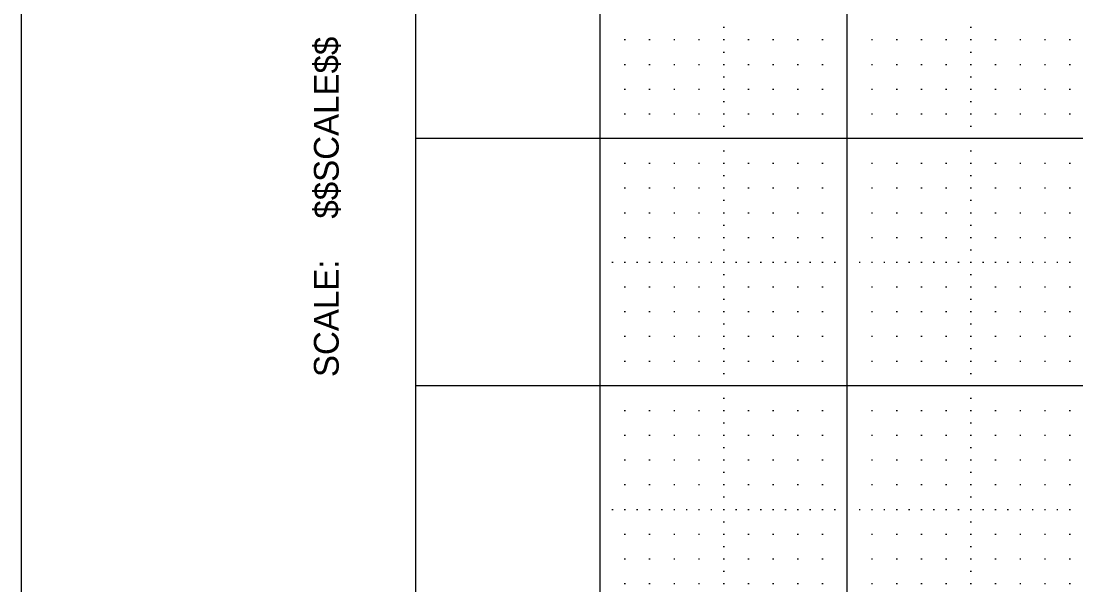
# Model space of a CAD drawing. Extents: x 0 to 34.3, y 0 to 22.
# Drawn here: x 0 to 4.268, y 3.214 to 5.495 of the extents above; entities that cross this region are included whole.
import ezdxf

# ---------------------------------------------------------------- set-up
doc = ezdxf.new("R2010")
doc.units = 0
for name, color, linetype in [('Level 1', 7, 'Continuous'), ('Level 5', 7, 'Continuous'), ('Level 63', 7, 'Continuous'), ('R_Border_Dark', 7, 'Continuous')]:
    doc.layers.add(name, color=color, linetype=linetype)

msp = doc.modelspace()

# ---------------------------------------------------------------- linework, layer by layer
at = {"layer": 'Level 1'}
msp.add_line((1.597, 0.726), (1.597, 21.272), dxfattribs=at)
msp.add_lwpolyline([(2.343, 9.02), (32.343, 9.02), (32.343, 1.02), (2.343, 1.02)], close=True, dxfattribs=at)
at = {"layer": 'Level 5'}
for p, q in [((2.8405, 5.47), (2.8455, 5.47)), ((3.8405, 5.47), (3.8455, 5.47)), ((2.4405, 5.42), (2.4455, 5.42)), ((2.5405, 5.42), (2.5455, 5.42)), ((2.6405, 5.42), (2.6455, 5.42)), ((2.7405, 5.42), (2.7455, 5.42)), ((2.8405, 5.42), (2.8455, 5.42)), ((2.9405, 5.42), (2.9455, 5.42)), ((3.0405, 5.42), (3.0455, 5.42)), ((3.1405, 5.42), (3.1455, 5.42)), ((3.2405, 5.42), (3.2455, 5.42)), ((3.4405, 5.42), (3.4455, 5.42)), ((3.5405, 5.42), (3.5455, 5.42)), ((3.6405, 5.42), (3.6455, 5.42)), ((3.7405, 5.42), (3.7455, 5.42)), ((3.8405, 5.42), (3.8455, 5.42)), ((3.9405, 5.42), (3.9455, 5.42)), ((4.0405, 5.42), (4.0455, 5.42)), ((4.1405, 5.42), (4.1455, 5.42)), ((4.2405, 5.42), (4.2455, 5.42)), ((2.8405, 5.37), (2.8455, 5.37)), ((3.8405, 5.37), (3.8455, 5.37)), ((2.4405, 5.32), (2.4455, 5.32)), ((2.5405, 5.32), (2.5455, 5.32)), ((2.6405, 5.32), (2.6455, 5.32)), ((2.7405, 5.32), (2.7455, 5.32)), ((2.8405, 5.32), (2.8455, 5.32)), ((2.9405, 5.32), (2.9455, 5.32)), ((3.0405, 5.32), (3.0455, 5.32)), ((3.1405, 5.32), (3.1455, 5.32)), ((3.2405, 5.32), (3.2455, 5.32)), ((3.4405, 5.32), (3.4455, 5.32)), ((3.5405, 5.32), (3.5455, 5.32)), ((3.6405, 5.32), (3.6455, 5.32)), ((3.7405, 5.32), (3.7455, 5.32)), ((3.8405, 5.32), (3.8455, 5.32)), ((3.9405, 5.32), (3.9455, 5.32)), ((4.0405, 5.32), (4.0455, 5.32)), ((4.1405, 5.32), (4.1455, 5.32)), ((4.2405, 5.32), (4.2455, 5.32)), ((2.8405, 5.27), (2.8455, 5.27)), ((3.8405, 5.27), (3.8455, 5.27)), ((2.4405, 5.22), (2.4455, 5.22)), ((2.5405, 5.22), (2.5455, 5.22)), ((2.6405, 5.22), (2.6455, 5.22)), ((2.7405, 5.22), (2.7455, 5.22)), ((2.8405, 5.22), (2.8455, 5.22)), ((2.9405, 5.22), (2.9455, 5.22)), ((3.0405, 5.22), (3.0455, 5.22)), ((3.1405, 5.22), (3.1455, 5.22)), ((3.2405, 5.22), (3.2455, 5.22)), ((3.4405, 5.22), (3.4455, 5.22)), ((3.5405, 5.22), (3.5455, 5.22)), ((3.6405, 5.22), (3.6455, 5.22)), ((3.7405, 5.22), (3.7455, 5.22)), ((3.8405, 5.22), (3.8455, 5.22)), ((3.9405, 5.22), (3.9455, 5.22)), ((4.0405, 5.22), (4.0455, 5.22)), ((4.1405, 5.22), (4.1455, 5.22)), ((4.2405, 5.22), (4.2455, 5.22)), ((2.8405, 5.17), (2.8455, 5.17)), ((3.8405, 5.17), (3.8455, 5.17)), ((2.4405, 5.12), (2.4455, 5.12)), ((2.5405, 5.12), (2.5455, 5.12)), ((2.6405, 5.12), (2.6455, 5.12)), ((2.7405, 5.12), (2.7455, 5.12)), ((2.8405, 5.12), (2.8455, 5.12)), ((2.9405, 5.12), (2.9455, 5.12)), ((3.0405, 5.12), (3.0455, 5.12)), ((3.1405, 5.12), (3.1455, 5.12)), ((3.2405, 5.12), (3.2455, 5.12)), ((3.4405, 5.12), (3.4455, 5.12)), ((3.5405, 5.12), (3.5455, 5.12)), ((3.6405, 5.12), (3.6455, 5.12)), ((3.7405, 5.12), (3.7455, 5.12)), ((3.8405, 5.12), (3.8455, 5.12)), ((3.9405, 5.12), (3.9455, 5.12)), ((4.0405, 5.12), (4.0455, 5.12)), ((4.1405, 5.12), (4.1455, 5.12)), ((4.2405, 5.12), (4.2455, 5.12)), ((2.8405, 5.07), (2.8455, 5.07)), ((3.8405, 5.07), (3.8455, 5.07)), ((2.8405, 4.97), (2.8455, 4.97)), ((3.8405, 4.97), (3.8455, 4.97)), ((2.4405, 4.92), (2.4455, 4.92)), ((2.5405, 4.92), (2.5455, 4.92)), ((2.6405, 4.92), (2.6455, 4.92)), ((2.7405, 4.92), (2.7455, 4.92)), ((2.8405, 4.92), (2.8455, 4.92)), ((2.9405, 4.92), (2.9455, 4.92)), ((3.0405, 4.92), (3.0455, 4.92)), ((3.1405, 4.92), (3.1455, 4.92)), ((3.2405, 4.92), (3.2455, 4.92)), ((3.4405, 4.92), (3.4455, 4.92)), ((3.5405, 4.92), (3.5455, 4.92)), ((3.6405, 4.92), (3.6455, 4.92)), ((3.7405, 4.92), (3.7455, 4.92)), ((3.8405, 4.92), (3.8455, 4.92)), ((3.9405, 4.92), (3.9455, 4.92)), ((4.0405, 4.92), (4.0455, 4.92)), ((4.1405, 4.92), (4.1455, 4.92)), ((4.2405, 4.92), (4.2455, 4.92)), ((2.8405, 4.87), (2.8455, 4.87)), ((3.8405, 4.87), (3.8455, 4.87)), ((2.4405, 4.82), (2.4455, 4.82)), ((2.5405, 4.82), (2.5455, 4.82)), ((2.6405, 4.82), (2.6455, 4.82)), ((2.7405, 4.82), (2.7455, 4.82)), ((2.8405, 4.82), (2.8455, 4.82)), ((2.9405, 4.82), (2.9455, 4.82)), ((3.0405, 4.82), (3.0455, 4.82)), ((3.1405, 4.82), (3.1455, 4.82)), ((3.2405, 4.82), (3.2455, 4.82)), ((3.4405, 4.82), (3.4455, 4.82)), ((3.5405, 4.82), (3.5455, 4.82)), ((3.6405, 4.82), (3.6455, 4.82)), ((3.7405, 4.82), (3.7455, 4.82)), ((3.8405, 4.82), (3.8455, 4.82)), ((3.9405, 4.82), (3.9455, 4.82)), ((4.0405, 4.82), (4.0455, 4.82)), ((4.1405, 4.82), (4.1455, 4.82)), ((4.2405, 4.82), (4.2455, 4.82)), ((2.8405, 4.77), (2.8455, 4.77)), ((3.8405, 4.77), (3.8455, 4.77)), ((2.4405, 4.72), (2.4455, 4.72)), ((2.5405, 4.72), (2.5455, 4.72)), ((2.6405, 4.72), (2.6455, 4.72)), ((2.7405, 4.72), (2.7455, 4.72)), ((2.8405, 4.72), (2.8455, 4.72)), ((2.9405, 4.72), (2.9455, 4.72)), ((3.0405, 4.72), (3.0455, 4.72)), ((3.1405, 4.72), (3.1455, 4.72)), ((3.2405, 4.72), (3.2455, 4.72)), ((3.4405, 4.72), (3.4455, 4.72)), ((3.5405, 4.72), (3.5455, 4.72)), ((3.6405, 4.72), (3.6455, 4.72)), ((3.7405, 4.72), (3.7455, 4.72)), ((3.8405, 4.72), (3.8455, 4.72)), ((3.9405, 4.72), (3.9455, 4.72)), ((4.0405, 4.72), (4.0455, 4.72)), ((4.1405, 4.72), (4.1455, 4.72)), ((4.2405, 4.72), (4.2455, 4.72)), ((2.8405, 4.67), (2.8455, 4.67)), ((3.8405, 4.67), (3.8455, 4.67)), ((2.4405, 4.62), (2.4455, 4.62)), ((2.5405, 4.62), (2.5455, 4.62)), ((2.6405, 4.62), (2.6455, 4.62)), ((2.7405, 4.62), (2.7455, 4.62)), ((2.8405, 4.62), (2.8455, 4.62)), ((2.9405, 4.62), (2.9455, 4.62)), ((3.0405, 4.62), (3.0455, 4.62)), ((3.1405, 4.62), (3.1455, 4.62)), ((3.2405, 4.62), (3.2455, 4.62)), ((3.4405, 4.62), (3.4455, 4.62)), ((3.5405, 4.62), (3.5455, 4.62)), ((3.6405, 4.62), (3.6455, 4.62)), ((3.7405, 4.62), (3.7455, 4.62)), ((3.8405, 4.62), (3.8455, 4.62)), ((3.9405, 4.62), (3.9455, 4.62)), ((4.0405, 4.62), (4.0455, 4.62)), ((4.1405, 4.62), (4.1455, 4.62)), ((4.2405, 4.62), (4.2455, 4.62)), ((2.8405, 4.57), (2.8455, 4.57)), ((3.8405, 4.57), (3.8455, 4.57)), ((2.3905, 4.52), (2.3955, 4.52)), ((2.4405, 4.52), (2.4455, 4.52)), ((2.4905, 4.52), (2.4955, 4.52)), ((2.5405, 4.52), (2.5455, 4.52)), ((2.5905, 4.52), (2.5955, 4.52)), ((2.6405, 4.52), (2.6455, 4.52)), ((2.6905, 4.52), (2.6955, 4.52)), ((2.7405, 4.52), (2.7455, 4.52)), ((2.7905, 4.52), (2.7955, 4.52)), ((2.8405, 4.52), (2.8455, 4.52)), ((2.8905, 4.52), (2.8955, 4.52)), ((2.9405, 4.52), (2.9455, 4.52)), ((2.9905, 4.52), (2.9955, 4.52)), ((3.0405, 4.52), (3.0455, 4.52)), ((3.0905, 4.52), (3.0955, 4.52)), ((3.1405, 4.52), (3.1455, 4.52)), ((3.1905, 4.52), (3.1955, 4.52)), ((3.2405, 4.52), (3.2455, 4.52)), ((3.2905, 4.52), (3.2955, 4.52)), ((3.3905, 4.52), (3.3955, 4.52)), ((3.4405, 4.52), (3.4455, 4.52)), ((3.4905, 4.52), (3.4955, 4.52)), ((3.5405, 4.52), (3.5455, 4.52)), ((3.5905, 4.52), (3.5955, 4.52)), ((3.6405, 4.52), (3.6455, 4.52)), ((3.6905, 4.52), (3.6955, 4.52)), ((3.7405, 4.52), (3.7455, 4.52)), ((3.7905, 4.52), (3.7955, 4.52)), ((3.8405, 4.52), (3.8455, 4.52)), ((3.8905, 4.52), (3.8955, 4.52)), ((3.9405, 4.52), (3.9455, 4.52)), ((3.9905, 4.52), (3.9955, 4.52)), ((4.0405, 4.52), (4.0455, 4.52)), ((4.0905, 4.52), (4.0955, 4.52)), ((4.1405, 4.52), (4.1455, 4.52)), ((4.1905, 4.52), (4.1955, 4.52)), ((4.2405, 4.52), (4.2455, 4.52)), ((2.8405, 4.47), (2.8455, 4.47)), ((3.8405, 4.47), (3.8455, 4.47)), ((2.4405, 4.42), (2.4455, 4.42)), ((2.5405, 4.42), (2.5455, 4.42)), ((2.6405, 4.42), (2.6455, 4.42)), ((2.7405, 4.42), (2.7455, 4.42)), ((2.8405, 4.42), (2.8455, 4.42)), ((2.9405, 4.42), (2.9455, 4.42)), ((3.0405, 4.42), (3.0455, 4.42)), ((3.1405, 4.42), (3.1455, 4.42)), ((3.2405, 4.42), (3.2455, 4.42)), ((3.4405, 4.42), (3.4455, 4.42)), ((3.5405, 4.42), (3.5455, 4.42)), ((3.6405, 4.42), (3.6455, 4.42)), ((3.7405, 4.42), (3.7455, 4.42)), ((3.8405, 4.42), (3.8455, 4.42)), ((3.9405, 4.42), (3.9455, 4.42)), ((4.0405, 4.42), (4.0455, 4.42)), ((4.1405, 4.42), (4.1455, 4.42)), ((4.2405, 4.42), (4.2455, 4.42)), ((2.8405, 4.37), (2.8455, 4.37)), ((3.8405, 4.37), (3.8455, 4.37)), ((2.4405, 4.32), (2.4455, 4.32)), ((2.5405, 4.32), (2.5455, 4.32)), ((2.6405, 4.32), (2.6455, 4.32)), ((2.7405, 4.32), (2.7455, 4.32)), ((2.8405, 4.32), (2.8455, 4.32)), ((2.9405, 4.32), (2.9455, 4.32)), ((3.0405, 4.32), (3.0455, 4.32)), ((3.1405, 4.32), (3.1455, 4.32)), ((3.2405, 4.32), (3.2455, 4.32)), ((3.4405, 4.32), (3.4455, 4.32)), ((3.5405, 4.32), (3.5455, 4.32)), ((3.6405, 4.32), (3.6455, 4.32)), ((3.7405, 4.32), (3.7455, 4.32)), ((3.8405, 4.32), (3.8455, 4.32)), ((3.9405, 4.32), (3.9455, 4.32)), ((4.0405, 4.32), (4.0455, 4.32)), ((4.1405, 4.32), (4.1455, 4.32)), ((4.2405, 4.32), (4.2455, 4.32)), ((2.8405, 4.27), (2.8455, 4.27)), ((3.8405, 4.27), (3.8455, 4.27)), ((2.4405, 4.22), (2.4455, 4.22)), ((2.5405, 4.22), (2.5455, 4.22)), ((2.6405, 4.22), (2.6455, 4.22)), ((2.7405, 4.22), (2.7455, 4.22)), ((2.8405, 4.22), (2.8455, 4.22)), ((2.9405, 4.22), (2.9455, 4.22)), ((3.0405, 4.22), (3.0455, 4.22)), ((3.1405, 4.22), (3.1455, 4.22)), ((3.2405, 4.22), (3.2455, 4.22)), ((3.4405, 4.22), (3.4455, 4.22)), ((3.5405, 4.22), (3.5455, 4.22)), ((3.6405, 4.22), (3.6455, 4.22)), ((3.7405, 4.22), (3.7455, 4.22)), ((3.8405, 4.22), (3.8455, 4.22)), ((3.9405, 4.22), (3.9455, 4.22)), ((4.0405, 4.22), (4.0455, 4.22)), ((4.1405, 4.22), (4.1455, 4.22)), ((4.2405, 4.22), (4.2455, 4.22)), ((2.8405, 4.17), (2.8455, 4.17)), ((3.8405, 4.17), (3.8455, 4.17)), ((2.4405, 4.12), (2.4455, 4.12)), ((2.5405, 4.12), (2.5455, 4.12)), ((2.6405, 4.12), (2.6455, 4.12)), ((2.7405, 4.12), (2.7455, 4.12)), ((2.8405, 4.12), (2.8455, 4.12)), ((2.9405, 4.12), (2.9455, 4.12)), ((3.0405, 4.12), (3.0455, 4.12)), ((3.1405, 4.12), (3.1455, 4.12)), ((3.2405, 4.12), (3.2455, 4.12)), ((3.4405, 4.12), (3.4455, 4.12)), ((3.5405, 4.12), (3.5455, 4.12)), ((3.6405, 4.12), (3.6455, 4.12)), ((3.7405, 4.12), (3.7455, 4.12)), ((3.8405, 4.12), (3.8455, 4.12)), ((3.9405, 4.12), (3.9455, 4.12)), ((4.0405, 4.12), (4.0455, 4.12)), ((4.1405, 4.12), (4.1455, 4.12)), ((4.2405, 4.12), (4.2455, 4.12)), ((2.8405, 4.07), (2.8455, 4.07)), ((3.8405, 4.07), (3.8455, 4.07)), ((2.8405, 3.97), (2.8455, 3.97)), ((3.8405, 3.97), (3.8455, 3.97)), ((2.4405, 3.92), (2.4455, 3.92)), ((2.5405, 3.92), (2.5455, 3.92)), ((2.6405, 3.92), (2.6455, 3.92)), ((2.7405, 3.92), (2.7455, 3.92)), ((2.8405, 3.92), (2.8455, 3.92)), ((2.9405, 3.92), (2.9455, 3.92)), ((3.0405, 3.92), (3.0455, 3.92)), ((3.1405, 3.92), (3.1455, 3.92)), ((3.2405, 3.92), (3.2455, 3.92)), ((3.4405, 3.92), (3.4455, 3.92)), ((3.5405, 3.92), (3.5455, 3.92)), ((3.6405, 3.92), (3.6455, 3.92)), ((3.7405, 3.92), (3.7455, 3.92)), ((3.8405, 3.92), (3.8455, 3.92)), ((3.9405, 3.92), (3.9455, 3.92)), ((4.0405, 3.92), (4.0455, 3.92)), ((4.1405, 3.92), (4.1455, 3.92)), ((4.2405, 3.92), (4.2455, 3.92)), ((2.8405, 3.87), (2.8455, 3.87)), ((3.8405, 3.87), (3.8455, 3.87)), ((2.4405, 3.82), (2.4455, 3.82)), ((2.5405, 3.82), (2.5455, 3.82)), ((2.6405, 3.82), (2.6455, 3.82)), ((2.7405, 3.82), (2.7455, 3.82)), ((2.8405, 3.82), (2.8455, 3.82)), ((2.9405, 3.82), (2.9455, 3.82)), ((3.0405, 3.82), (3.0455, 3.82)), ((3.1405, 3.82), (3.1455, 3.82)), ((3.2405, 3.82), (3.2455, 3.82)), ((3.4405, 3.82), (3.4455, 3.82)), ((3.5405, 3.82), (3.5455, 3.82)), ((3.6405, 3.82), (3.6455, 3.82)), ((3.7405, 3.82), (3.7455, 3.82)), ((3.8405, 3.82), (3.8455, 3.82)), ((3.9405, 3.82), (3.9455, 3.82)), ((4.0405, 3.82), (4.0455, 3.82)), ((4.1405, 3.82), (4.1455, 3.82)), ((4.2405, 3.82), (4.2455, 3.82)), ((2.8405, 3.77), (2.8455, 3.77)), ((3.8405, 3.77), (3.8455, 3.77)), ((2.4405, 3.72), (2.4455, 3.72)), ((2.5405, 3.72), (2.5455, 3.72)), ((2.6405, 3.72), (2.6455, 3.72)), ((2.7405, 3.72), (2.7455, 3.72)), ((2.8405, 3.72), (2.8455, 3.72)), ((2.9405, 3.72), (2.9455, 3.72)), ((3.0405, 3.72), (3.0455, 3.72)), ((3.1405, 3.72), (3.1455, 3.72)), ((3.2405, 3.72), (3.2455, 3.72)), ((3.4405, 3.72), (3.4455, 3.72)), ((3.5405, 3.72), (3.5455, 3.72)), ((3.6405, 3.72), (3.6455, 3.72)), ((3.7405, 3.72), (3.7455, 3.72)), ((3.8405, 3.72), (3.8455, 3.72)), ((3.9405, 3.72), (3.9455, 3.72)), ((4.0405, 3.72), (4.0455, 3.72)), ((4.1405, 3.72), (4.1455, 3.72)), ((4.2405, 3.72), (4.2455, 3.72)), ((2.8405, 3.67), (2.8455, 3.67)), ((3.8405, 3.67), (3.8455, 3.67)), ((2.4405, 3.62), (2.4455, 3.62)), ((2.5405, 3.62), (2.5455, 3.62)), ((2.6405, 3.62), (2.6455, 3.62)), ((2.7405, 3.62), (2.7455, 3.62)), ((2.8405, 3.62), (2.8455, 3.62)), ((2.9405, 3.62), (2.9455, 3.62)), ((3.0405, 3.62), (3.0455, 3.62)), ((3.1405, 3.62), (3.1455, 3.62)), ((3.2405, 3.62), (3.2455, 3.62)), ((3.4405, 3.62), (3.4455, 3.62)), ((3.5405, 3.62), (3.5455, 3.62)), ((3.6405, 3.62), (3.6455, 3.62)), ((3.7405, 3.62), (3.7455, 3.62)), ((3.8405, 3.62), (3.8455, 3.62)), ((3.9405, 3.62), (3.9455, 3.62)), ((4.0405, 3.62), (4.0455, 3.62)), ((4.1405, 3.62), (4.1455, 3.62)), ((4.2405, 3.62), (4.2455, 3.62)), ((2.8405, 3.57), (2.8455, 3.57)), ((3.8405, 3.57), (3.8455, 3.57)), ((2.3905, 3.52), (2.3955, 3.52)), ((2.4405, 3.52), (2.4455, 3.52)), ((2.4905, 3.52), (2.4955, 3.52)), ((2.5405, 3.52), (2.5455, 3.52)), ((2.5905, 3.52), (2.5955, 3.52)), ((2.6405, 3.52), (2.6455, 3.52)), ((2.6905, 3.52), (2.6955, 3.52)), ((2.7405, 3.52), (2.7455, 3.52)), ((2.7905, 3.52), (2.7955, 3.52)), ((2.8405, 3.52), (2.8455, 3.52)), ((2.8905, 3.52), (2.8955, 3.52)), ((2.9405, 3.52), (2.9455, 3.52)), ((2.9905, 3.52), (2.9955, 3.52)), ((3.0405, 3.52), (3.0455, 3.52)), ((3.0905, 3.52), (3.0955, 3.52)), ((3.1405, 3.52), (3.1455, 3.52)), ((3.1905, 3.52), (3.1955, 3.52)), ((3.2405, 3.52), (3.2455, 3.52)), ((3.2905, 3.52), (3.2955, 3.52)), ((3.3905, 3.52), (3.3955, 3.52)), ((3.4405, 3.52), (3.4455, 3.52)), ((3.4905, 3.52), (3.4955, 3.52)), ((3.5405, 3.52), (3.5455, 3.52)), ((3.5905, 3.52), (3.5955, 3.52)), ((3.6405, 3.52), (3.6455, 3.52)), ((3.6905, 3.52), (3.6955, 3.52)), ((3.7405, 3.52), (3.7455, 3.52)), ((3.7905, 3.52), (3.7955, 3.52)), ((3.8405, 3.52), (3.8455, 3.52)), ((3.8905, 3.52), (3.8955, 3.52)), ((3.9405, 3.52), (3.9455, 3.52)), ((3.9905, 3.52), (3.9955, 3.52)), ((4.0405, 3.52), (4.0455, 3.52)), ((4.0905, 3.52), (4.0955, 3.52)), ((4.1405, 3.52), (4.1455, 3.52)), ((4.1905, 3.52), (4.1955, 3.52)), ((4.2405, 3.52), (4.2455, 3.52)), ((2.8405, 3.47), (2.8455, 3.47)), ((3.8405, 3.47), (3.8455, 3.47)), ((2.4405, 3.42), (2.4455, 3.42)), ((2.5405, 3.42), (2.5455, 3.42)), ((2.6405, 3.42), (2.6455, 3.42)), ((2.7405, 3.42), (2.7455, 3.42)), ((2.8405, 3.42), (2.8455, 3.42)), ((2.9405, 3.42), (2.9455, 3.42)), ((3.0405, 3.42), (3.0455, 3.42)), ((3.1405, 3.42), (3.1455, 3.42)), ((3.2405, 3.42), (3.2455, 3.42)), ((3.4405, 3.42), (3.4455, 3.42)), ((3.5405, 3.42), (3.5455, 3.42)), ((3.6405, 3.42), (3.6455, 3.42)), ((3.7405, 3.42), (3.7455, 3.42)), ((3.8405, 3.42), (3.8455, 3.42)), ((3.9405, 3.42), (3.9455, 3.42)), ((4.0405, 3.42), (4.0455, 3.42)), ((4.1405, 3.42), (4.1455, 3.42)), ((4.2405, 3.42), (4.2455, 3.42)), ((2.8405, 3.37), (2.8455, 3.37)), ((3.8405, 3.37), (3.8455, 3.37)), ((2.4405, 3.32), (2.4455, 3.32)), ((2.5405, 3.32), (2.5455, 3.32)), ((2.6405, 3.32), (2.6455, 3.32)), ((2.7405, 3.32), (2.7455, 3.32)), ((2.8405, 3.32), (2.8455, 3.32)), ((2.9405, 3.32), (2.9455, 3.32)), ((3.0405, 3.32), (3.0455, 3.32)), ((3.1405, 3.32), (3.1455, 3.32)), ((3.2405, 3.32), (3.2455, 3.32)), ((3.4405, 3.32), (3.4455, 3.32)), ((3.5405, 3.32), (3.5455, 3.32)), ((3.6405, 3.32), (3.6455, 3.32)), ((3.7405, 3.32), (3.7455, 3.32)), ((3.8405, 3.32), (3.8455, 3.32)), ((3.9405, 3.32), (3.9455, 3.32)), ((4.0405, 3.32), (4.0455, 3.32)), ((4.1405, 3.32), (4.1455, 3.32)), ((4.2405, 3.32), (4.2455, 3.32)), ((2.8405, 3.27), (2.8455, 3.27)), ((3.8405, 3.27), (3.8455, 3.27)), ((2.4405, 3.22), (2.4455, 3.22)), ((2.5405, 3.22), (2.5455, 3.22)), ((2.6405, 3.22), (2.6455, 3.22)), ((2.7405, 3.22), (2.7455, 3.22)), ((2.8405, 3.22), (2.8455, 3.22)), ((2.9405, 3.22), (2.9455, 3.22)), ((3.0405, 3.22), (3.0455, 3.22)), ((3.1405, 3.22), (3.1455, 3.22)), ((3.2405, 3.22), (3.2455, 3.22)), ((3.4405, 3.22), (3.4455, 3.22)), ((3.5405, 3.22), (3.5455, 3.22)), ((3.6405, 3.22), (3.6455, 3.22)), ((3.7405, 3.22), (3.7455, 3.22)), ((3.8405, 3.22), (3.8455, 3.22)), ((3.9405, 3.22), (3.9455, 3.22)), ((4.0405, 3.22), (4.0455, 3.22)), ((4.1405, 3.22), (4.1455, 3.22)), ((4.2405, 3.22), (4.2455, 3.22))]:
    msp.add_line(p, q, dxfattribs=at)
at = {"layer": 'Level 63'}
msp.add_lwpolyline([(0, 0), (34, 0), (34, 22), (0, 22)], close=True, dxfattribs=at)
msp.add_lwpolyline([(32.343, 9.02), (32.343, 1.02), (2.343, 1.02), (2.343, 9.02)], dxfattribs=at)
at = {"layer": 'R_Border_Dark'}
for p, q in [((2.343, 1.02), (2.343, 9.02)), ((3.343, 1.02), (3.343, 9.02)), ((33.215, 5.02), (1.597, 5.02)), ((33.215, 4.02), (1.597, 4.02))]:
    msp.add_line(p, q, dxfattribs=at)
msp.add_lwpolyline([(32.343, 9.02), (32.343, 1.02), (2.343, 1.02), (2.343, 9.02)], dxfattribs=at)

# ---------------------------------------------------------------- texts
at = {"layer": 'Level 1'}
for s, p in [('$$SCALE$$', (1.285, 4.696)), ('SCALE:', (1.285, 4.055))]:
    msp.add_text(s, height=0.1, rotation=90, dxfattribs=at).set_placement(p)

doc.saveas('drawing.dxf')
